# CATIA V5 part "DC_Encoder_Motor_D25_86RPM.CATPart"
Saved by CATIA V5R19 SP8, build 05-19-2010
Part number: DC Encoder Motor_D25_86RPM
Definition: DC Encoder Motor_D25_86RPM
Nomenclature: 80042
Source: Unknown
Description: 9V
Bounding box of the stored display mesh (mm): x -13.5 to 13.5, y -13.49 to 18.027, z -25 to 65
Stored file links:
  D:\Documents\1_Travail\1 - ac-limoges.fr\ac-limoges.fr\Emmanuel Maynard - STI2D_Turgot\1 - IT-I2D\Activités_IT_Première\IT_3_Abris_bus\Maquettes numériques\Abribus_eleve\DC_Encoder_Motor_D25_86RPM.CATPart
  C:\Program Files\Dassault Systemes\B19\win_b64\reffiles\standard\MetricThickPitch.txt
  D:\Documents\1_Travail\2- 2I2D\6 -  Ressources ITEC\Ressources Techniques\0-Maquettes numériques_Composants\Catalogue_Makeblock\Catalog_Makeblock\09_Moteurs\TableMoteur_D25.xls
  C:\ProgramData\DassaultSystemes\Catalogues_Catia\Catalog_Makeblock\09_Moteurs\TableMoteurs_D25.xls
  D:\Documents\1_Travail\2- 2I2D\6 -  Ressources ITEC\Ressources Techniques\0-Maquettes numériques_Composants\Catalogue_Makeblock\Catalog_Makeblock\09_Moteurs\TableMoteur_D25.txt
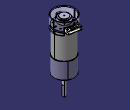
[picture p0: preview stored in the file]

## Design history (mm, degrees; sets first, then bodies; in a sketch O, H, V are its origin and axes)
Parameters
  `Longueur_Réducteur` = 21 mm
  `Désignation` = "DC Encoder Motor_D25_86RPM"
  `Référence` = "80042"
  Observation = "9V"
  Encodeur = true
AxisSystem1: origin (0, 0, 0), X (1, 0, 0), Y (0, 1, 0), Z (0, 0, 1)
Body1 "Réducteur" (main body)
  Sketch1 on YZ plane of AxisSystem1, origin (0, 0, 0), H (0, 1, 0), V (0, 0, 1)
    axis line L1 (0, 22.4596) -> (0, -27.2317)
    point P1 (0, 22.4596)
    point P3 (0, 21)
    line L2 (0, 21) -> (12.5, 21)
    line L3 (12.5, 21) -> (12.5, 0)
    point P5 (12.5, 0)
    line L4 (12.5, 0) -> (3.5, 0)
    line L5 (3.5, 0) -> (3.5, -2.5)
    line L6 (3.5, -2.5) -> (2, -2.5)
    line L7 (2, -2.5) -> (2, -25)
    line L8 (2, -25) -> (0, -25)
    point P10 (0, -25)
    distance L7 L1 = 2
    distance L5 L1 = 3.5
    distance L3 L1 = 12.5
    distance L6 L4 = 2.5
    distance L8 L6 = 22.5
    distance L2 L4 = 21 {= `Longueur_Réducteur`}
    coincidence: P1 V, P3 L1, P5 H, P10 L1
    vertical: L1 V, L3 V, L5 V, L7 V
    horizontal: L2 H, L4 H, L6 H, L8 H
  Shaft1: profile Sketch1, axis Sketch1.L1, angle 360
  Sketch2 on ZX plane of AxisSystem1, origin (0, 0, 0), H (0, 0, 1), V (1, 0, 0)
    line L1 (-25, 2.5) -> (-12, 2.5)
    line L2 (-12, 2.5) -> (-12, 1.5)
    line L3 (-12, 1.5) -> (-25, 1.5)
    line L4 (-25, 1.5) -> (-25, 2.5)
    reference intersected line E1 (-25, -2) -> (-25, 2) from face of Shaft1 from Sketch1.L8
    reference projected line E2 through (0, 0) direction (-1, 0) from axis of face of Shaft1 from Sketch1.L7
    distance L2 L4 = 13
    distance L3 E2 = 1.5
    distance L1 L3 = 1
    horizontal: L1 H, L3 H
    vertical: L2 V, L4 V
    coincidence: L4 E1
  Pocket1: profile Sketch2, direction (0, -1, 0), through (limit type 3), opposite side through (limit type 3)
  Fillet1: radius 1, on edge [face of Shaft1 from Sketch1.L3 | face of Shaft1 from Sketch1.L4]
  Chamfer1: length 0.25, angle 45, on edge [face of Shaft1 from Sketch1.L7 | face of Shaft1 from Sketch1.L8]; edge [face of Shaft1 from Sketch1.L5 | face of Shaft1 from Sketch1.L6]
  Sketch3 on face of Shaft1 from Sketch1.L4, origin (0.0943, 8.5797, 0), H (1, 0, 0), V (0, -1, 0)
    point P1 (-0.0943, 0.0797)
    reference projected point E1 (-0.0943, 8.5797) from axis of face of Shaft1 from Sketch1.L7
    reference projected line E2 through (-0.0943, 0) direction (0, -1) from edge [YZ plane of AxisSystem1 | XY plane of AxisSystem1]
    distance P1 E1 = 8.5
    coincidence: P1 E2
  Hole1: placed by Sketch3, at (0, 8.5, 0) direction (0, 0, 1), diameter 2.459, depth 10, threaded "M3", thread diameter 3, thread depth 10, pitch 0.5
  Sketch4 on face of Shaft1 from Sketch1.L4, origin (-8.4826, -0.0028, 0), H (1, 0, 0), V (0, -1, 0)
    point P1 (-0.0174, -0.0028)
    reference projected point E1 (8.4826, -0.0028) from axis of face of Shaft1 from Sketch1.L7
    reference projected line E2 through (0, -0.0028) direction (1, 0) from edge [XY plane of AxisSystem1 | ZX plane of AxisSystem1]
    distance P1 E1 = 8.5
    coincidence: E2 P1
  Hole2: placed by Sketch4, at (-8.5, 0, 0) direction (0, 0, 1), diameter 2.5, depth 10, counterbore diameter 4.8, counterbore depth 2.5
  CircPattern1: of Hole1, Hole2, instances 2, angular step 180, axis from face of Shaft1 from Sketch1.L7
Body2 "Moteur"
  Solid1 "DC Motor 25mm V2.0 -1-solid1": solid without history
  Split1: SplitPlane face of Solid1
  Body3 "Cross recessed pan head screw M2£®5¡Á18-1-solid1"
    Solid2: solid without history
  Add1: tool Body3
  Body4 "Cross recessed pan head screw M2£®5¡Á18-2-solid1"
    Solid3: solid without history
  Add2: tool Body4
  Body5 "25_motor_backboard assembly -1/C1-1/774087856-1/Extruded_1-1-solid1"
    Solid4: solid without history
  Add3: tool Body5
  Body6 "25_motor_backboard assembly -1/C2-1/774087856-1/Extruded_1-1-solid1"
    Solid5: solid without history
  Add4: tool Body6
  Body7 "25_motor_backboard assembly -1/C3-1/774131120-1/Extruded_1_2-1-solid1"
    Solid6: solid without history
  Add5: tool Body7
  Body8 "25_motor_backboard assembly -1/C4-1/774131120-1/Extruded_1_2-1-solid1"
    Solid7: solid without history
  Add6: tool Body8
  Body9 "25_motor_backboard assembly -1/L1-1/R0603-1-solid1"
    Solid8: solid without history
  Add7: tool Body9
  Body10 "25_motor_backboard assembly -1/L1-1/R0603-1-solid2"
    Solid9: solid without history
  Add8: tool Body10
  Body11 "25_motor_backboard assembly -1/L2-1/R0603-1-solid1"
    Solid10: solid without history
  Add9: tool Body11
  Body12 "25_motor_backboard assembly -1/L2-1/R0603-1-solid2"
    Solid11: solid without history
  Add10: tool Body12
  Body13 "25_motor_backboard assembly -1/R1-1/R0603-1-solid1"
    Solid12: solid without history
  Add11: tool Body13
  Body14 "25_motor_backboard assembly -1/R1-1/R0603-1-solid2"
    Solid13: solid without history
  Add12: tool Body14
  Body15 "25_motor_backboard assembly -1/R2-1/R0603-1-solid1"
    Solid14: solid without history
  Add13: tool Body15
  Body16 "25_motor_backboard assembly -1/R2-1/R0603-1-solid2"
    Solid15: solid without history
  Add14: tool Body16
  Body17 "25_motor_backboard assembly -1/Hall sensor-1/Hall sensor base -1-solid1"
    Solid16: solid without history
  Add15: tool Body17
  Body18
    Solid17 "25_motor_backboard assembly -1/Board_1-1-solid1": solid without history
  Add16: tool Body18
  Body19 "25_motor_backboard assembly -1/½ÓÏß×ù-1-solid1"
    Solid18: solid without history
  Add17: tool Body19
  Body20 "Codeur"
    Body21 "25_motor_backboard assembly -1/Hall sensor-1/Hall sensor-1-solid1"
      Solid19: solid without history
    Add18: tool Body21
    Body22 "25mm DC motor »·ÐÎ´ÅÌú¹Ì¶¨¿é-1-solid1"
      Solid20: solid without history
    Add19: tool Body22
    Body23 "»·ÐÎ´ÅÌú-1-solid1"
      Solid21: solid without history
    Add20: tool Body23
    Body24
      Plane1: type Offset, RefPlane XY plane of AxisSystem1, Offset 50
      Sketch5 on Plane1, origin (0, 0, 50), H (1, 0, 0), V (0, -1, 0)
        circle A1 centre (0, 0) radius 13.5
        radius A1 = 13.5
      Pad1: profile Sketch5, direction (0, 0, 1), length 15
      Shell1: IntOffset 1, Face start face of Pad1, ExtOffset 0
      Plane2: type Angle, RefPlane ZX plane of AxisSystem1, Direction edge [ZX plane of AxisSystem1 | YZ plane of AxisSystem1], Angle -10
      Sketch6 on Plane2, origin (0, 0, 0), H (0.9848, -0.1736, 0), V (0, 0, 1)
        line L1 (7.4, 58.7711) -> (-7.4, 58.7711)
        line L2 (-7.4, 58.7711) -> (-7.4, 50)
        line L3 (-7.4, 50) -> (7.4, 50)
        line L4 (7.4, 50) -> (7.4, 58.7711)
        reference intersected line E1 (13.5, 50) -> (-13.5, 50) from start face of Pad1
        distance L3 L1 = 8.7711
        distance L4 L2 = 14.8
        distance L4 V = 7.4
        horizontal: L1 H, L3 H
        vertical: L2 V, L4 V
        coincidence: L3 E1
      Pocket2: profile Sketch6, direction (0.1736, 0.9848, 0), through (limit type 3)
      Fillet2: radius 0.5, on end face of Pad1
    Add21: tool Body24
  Add22: tool Body20
Relations
  Add22.Activity = Encodeur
